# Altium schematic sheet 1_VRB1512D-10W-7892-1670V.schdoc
size 289 x 200 mm; Name: default297x210; Symbol: default297x210; Device: default297x210; Date: 2025.05.23; Rev: V1.0; Size: "A4"; Id: /; File: VRB1512-10W-7892-1670V; Sheet: /; @Page No: 1; @Page Count: 1; @Schematic Name: VRB1512D-10W-7892-1670V; @Project Name: VRB1512D-10W-7892-1670V; @Board Name: VRB1512D-10W-7892-1670V; @Update Date: 2025-05-28; @Create Time: 17:45:47; @Update Time: 14:18:29; @Page Name: VRB1512D-10W-7892-1670V; @Create Date: 2025-05-23
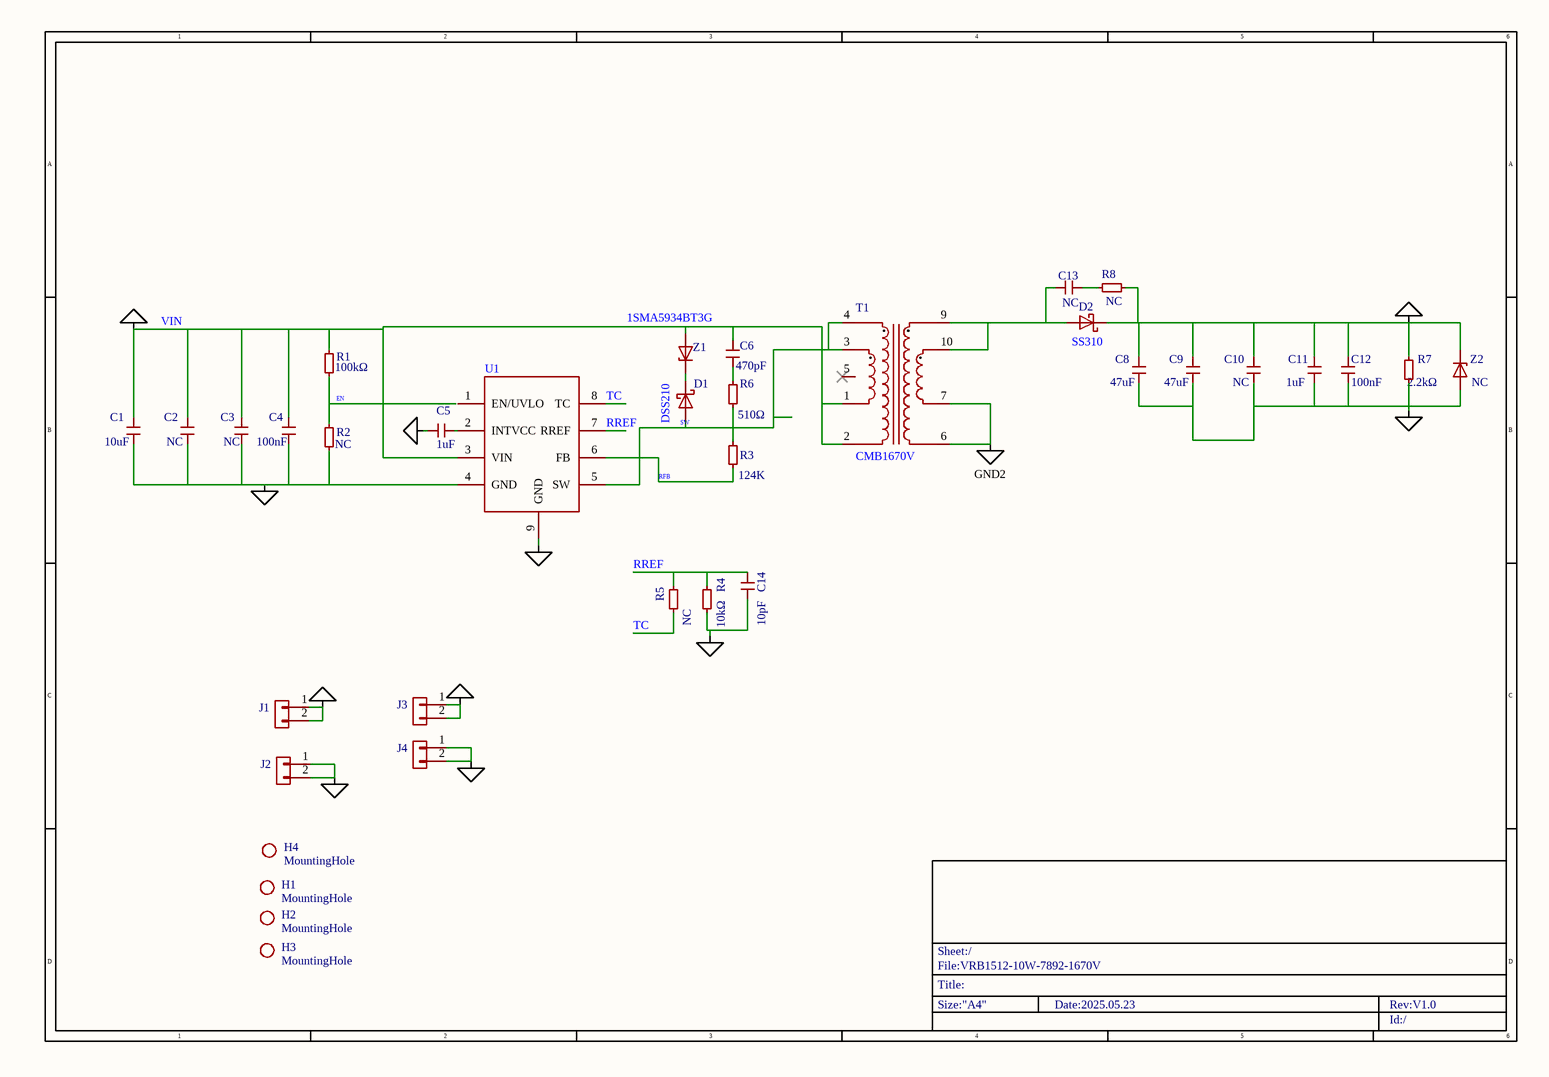
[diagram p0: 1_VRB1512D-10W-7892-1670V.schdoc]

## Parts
C1  10uF  [C1206]
C2  value NC  [C1206]  (hidden comment: MY_C)
C3  value NC  [C0805]  (hidden comment: MY_C)
C4  100nF  [C0603]
C5  1uF  [C0603]
C6  470pF  [C0603]
C8  47uF  [C1206]
C9  47uF  [C1206]
C10  value NC  [MYLibrary:C1206]  (hidden comment: MY_C)
C11  1uF  [C0805]
C12  100nF  [C0603]
C13  value NC  [C0603]  (hidden comment: My_library_C)
C14  10pF  [C0603]
D1  DSS210  [SOD-123_L2.8-W1.8-LS3.7-FD]
D2  SS310  [SMA_L4.3-W2.6-LS5.2-RD]
H1  value MountingHole  [MountingHole:MountingHole_3.2mm_M3_DIN965]  (hidden comment: Mechanical_MountingHole)
H2  value MountingHole  [MountingHole:MountingHole_3.2mm_M3_DIN965]  (hidden comment: Mechanical_MountingHole)
H3  value MountingHole  [MountingHole:MountingHole_3.2mm_M3_DIN965]  (hidden comment: Mechanical_MountingHole)
H4  value MountingHole  [MountingHole:MountingHole_3.2mm_M3_DIN965]  (hidden comment: Mechanical_MountingHole)
J1  Connector_Generic_Conn_01x02  [Connector_PinHeader_2.54mm:PinHeader_1x02_P2.54mm_Vertical]  (value not drawn)
J2  Connector_Generic_Conn_01x02  [Connector_PinHeader_2.54mm:PinHeader_1x02_P2.54mm_Vertical]  (value not drawn)
J3  Connector_Generic_Conn_01x02  [Connector_PinHeader_2.54mm:PinHeader_1x02_P2.54mm_Vertical]  (value not drawn)
J4  Connector_Generic_Conn_01x02  [Connector_PinHeader_2.54mm:PinHeader_1x02_P2.54mm_Vertical]  (value not drawn)
R1  100kΩ  [R0603]
R2  value NC  [MYLibrary:R0603]  (hidden comment: Device_R_Small)
R3  value 124K  [MYLibrary:R0603]  (hidden comment: Device_R_Small)
R4  10kΩ  [R0603]
R5  value NC  [R0603]  (hidden comment: Device_R_Small)
R6  510Ω  [R0603]
R7  2.2kΩ  [R0603]
R8  value NC  [R0603]  (hidden comment: Device_R_Small)
T1  CMB1670V  [XFMR-SMD_CMB1670V]
U1  (no value)  [ESOP-8_L4.9-W3.9-P1.27-LS6.0-TL-EP3.3]
Z1  1SMA5934BT3G  [SMA_L4.3-W2.6-LS5.2-RD]
Z2  value NC  [DIODE-SMA]  (hidden comment: Diode_BZV55C75)

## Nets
GND1: C1.2 C2.2 C3.2 C4.1 C5.1 C14.1 J2.1(Pin_1) J2.2(Pin_2) R2.2 R4.2 U1.4(GND) U1.9(GND)
GND2: C8.2 C9.2 C10.2 C11.2 C12.1 J4.1(Pin_1) J4.2(Pin_2) R7.1 T1.6 T1.7 Z2.2(A)
VIN: C1.1 C2.1 C3.1 C4.2 C6.1 J1.1(Pin_1) J1.2(Pin_2) R1.1 T1.1 T1.2 U1.3(VIN) Z1.2(A)
VOUT: C8.1 C9.1 C10.1 C11.1 C12.2 D2.1(K) J3.1(Pin_1) J3.2(Pin_2) R7.2 R8.1 Z2.1(K)
EN: R1.2 R2.1
RFB: R3.1 U1.6(FB)
RREF: C14.2 R4.1 R5.2 U1.7(RREF)
SW: D1.2(A) R3.2 R6.1 T1.3 T1.4 U1.5(SW)
TC: R5.1 U1.8(TC)
NetC5_2: C5.2 U1.2(INTVCC)
NetC6_2: C6.2 R6.2
NetC13_1: C13.1 R8.2
NetC13_2: C13.2 D2.2(A) T1.9 T1.10
NetD1_1: D1.1(K) Z1.1(K)

Not connected (* = marked no-connect by the designer): T1 5*; U1 1(EN/UVLO)

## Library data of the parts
C1 = CC1206KKX5R9BB106: Manufacturer: YAGEO(国巨); Symbol: MY_C; Add into BOM: yes; Tolerance: ±10%; Voltage Rated: 50V; Temperature Coefficient: X5R
C2 = MY_C: Users: REF**; ki_fp_filters: C_*; Add into BOM: yes; Origin Footprint: MYLibrary:C1206
C3 = MY_C: Users: REF**; ki_fp_filters: C_*; Add into BOM: yes; Origin Footprint: MYLibrary:C0805
C4 C12 = CC0603KRX7R9BB104: Manufacturer: YAGEO(国巨); Symbol: MY_C; Add into BOM: yes; Tolerance: ±10%; Voltage Rated: 50V; Temperature Coefficient: X7R
C5 = CC0603KRX7R9BB105: Manufacturer: YAGEO(国巨); Symbol: MY_C; Add into BOM: yes; Tolerance: ±10%; Voltage Rated: 50V; Temperature Coefficient: X7R
C6 = CC0603KRX7R9BB471: Manufacturer: YAGEO(国巨); Symbol: My_library_C; Add into BOM: yes; Tolerance: ±10%; Voltage Rated: 50V; Temperature Coefficient: X7R
C8 C9 = CGA1206X5R476M250NT: Manufacturer: HRE(芯声); Symbol: MY_C; Add into BOM: yes; Tolerance: ±20%; Voltage Rated: 25V; Temperature Coefficient: X5R
C10 = MY_C: Users: REF**; ki_fp_filters: C_*; Add into BOM: yes
C11 = CC0805KKX7R9BB105: Manufacturer: YAGEO(国巨); Symbol: MY_C; Add into BOM: yes; Tolerance: ±10%; Voltage Rated: 50V; Temperature Coefficient: X7R
C13 = My_library_C: Add into BOM: yes; Origin Footprint: MYLibrary:C0603
C14 = CC0603JRNPO9BN100: Manufacturer: YAGEO(国巨); Symbol: My_library_C; Add into BOM: yes; Tolerance: ±5%; Voltage Rated: 50V; Temperature Coefficient: NP0
D1 = DSS210: Manufacturer: CJ(江苏长电/长晶); Symbol: My library_DSS210; Add into BOM: yes; Diode Configuration: 独立式; Forward Voltage (Vf@If): 850mV@2A; Reverse Voltage (Vr): 100V; Rectified Current: 2A; Reverse Leakage Current (Ir): 100uA@100V
D2 = SS310_C15874: Manufacturer: MDD(辰达半导体); Symbol: My library_DSS210; Add into BOM: yes; Diode Configuration: 独立式; Forward Voltage (Vf@If): 850mV@3A; Reverse Voltage (Vr): 100V; Rectified Current: 3A; Reverse Leakage Current (Ir): 500uA@100V
H1-H4 = Mechanical_MountingHole: Users: REF**; ki_fp_filters: MountingHole*; Add into BOM: yes
J1-J4 = Connector_Generic_Conn_01x02: Users: REF**; ki_fp_filters: Connector*:*_1x??_*; Add into BOM: yes
R1 = RC0603FR-07100KL: Manufacturer: YAGEO(国巨); Symbol: Device_R_Small; Add into BOM: yes; Tolerance: ±1%; Power(Watts): 100mW; Overload Voltage (Max): 75V; Temperature Coefficient: ±100ppm/℃
R2 R3 = Device_R_Small: Users: REF**; ki_fp_filters: R_*; Add into BOM: yes
R4 = RC0603FR-0710KL: Manufacturer: YAGEO(国巨); Symbol: Device_R_Small; Add into BOM: yes; Tolerance: ±1%; Power(Watts): 100mW; Overload Voltage (Max): 75V; Temperature Coefficient: ±100ppm/℃
R5 R8 = Device_R_Small: Users: REF**; ki_fp_filters: R_*; Add into BOM: yes; Origin Footprint: MYLibrary:R0603
R6 = RC0603FR-07510RL: Manufacturer: YAGEO(国巨); Symbol: Device_R_Small; Add into BOM: yes; Tolerance: ±1%; Power(Watts): 100mW; Overload Voltage (Max): 75V; Temperature Coefficient: ±100ppm/℃
R7 = RC0603FR-072K2L: Manufacturer: YAGEO(国巨); Symbol: Device_R_Small; Add into BOM: yes; Tolerance: ±1%; Power(Watts): 100mW; Voltage-Supply(Max): 75V; Temperature Coefficient: ±100ppm/℃
T1 = CMB1670V: Manufacturer: coileasy(线易); Add into BOM: yes
U1 = CMP7892: Add into BOM: yes
Z1 = 1SMA5934BT3G: Manufacturer: onsemi(安森美); Symbol: Diode_BZV55C75; Add into BOM: yes; Diode Configuration: 独立式; Zener Voltage (Nom): 24V; Reverse Leakage Current (Ir): 500nA@18.2V; Zener Voltage (Range): 22.8V~24V; Power Dissipation: 1.5W; Zener Impedance (Zzt): 19Ω
Z2 = Diode_BZV55C75: Users: REF**; ki_fp_filters: D*MiniMELF*; Add into BOM: yes; Origin Footprint: Diode_SMD:D_SMA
